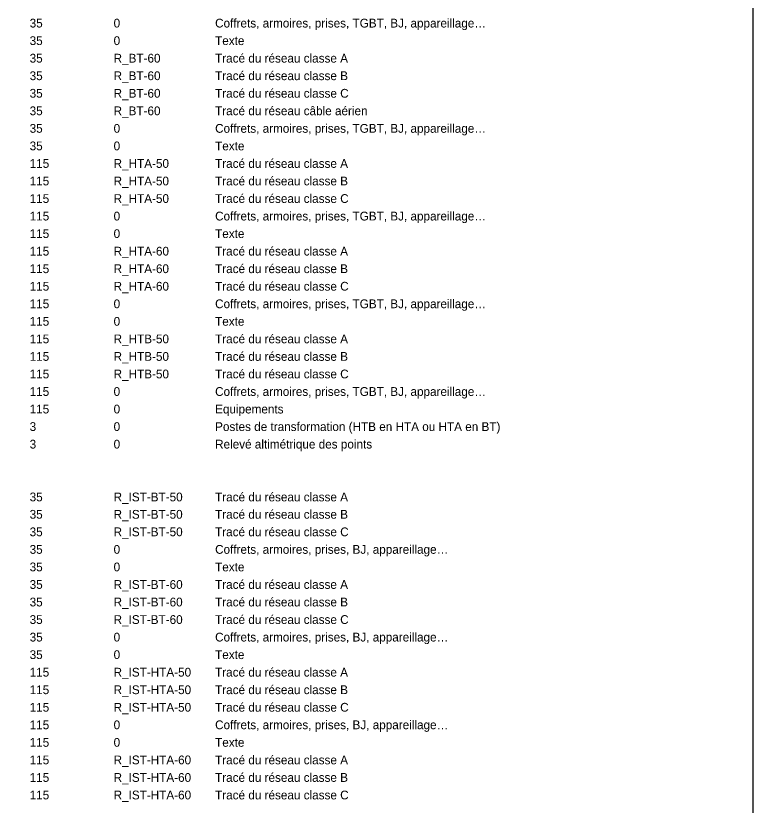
# Model space of a CAD drawing. Extents: x -60 to 214, y -380 to -21.
# Drawn here: x 72.77 to 114.84, y -110.94 to -65.94 of the extents above; entities that cross this region are included whole.
import ezdxf

# ---------------------------------------------------------------- set-up
doc = ezdxf.new("R2010")
doc.units = 0
for name, color, linetype in [('Default', 7, 'Continuous'), ('DH_TEXTE', 7, 'Continuous'), ('R_ELEC_ALT_POINT', 7, 'Continuous'), ('R_ELEC_BT_50HZ_EQUIP', 7, 'Continuous'), ('R_ELEC_BT_50HZ_TEXTE', 7, 'Continuous'), ('R_ELEC_BT_60HZ_EQUIP', 7, 'Continuous'), ('R_ELEC_BT_60HZ_LIAISON_CL_A', 7, 'Continuous'), ('R_ELEC_BT_60HZ_LIAISON_CL_B', 7, 'Continuous'), ('R_ELEC_BT_60HZ_LIAISON_CL_C', 7, 'Continuous'), ('R_ELEC_BT_60HZ_TEXTE', 7, 'Continuous'), ('R_ELEC_HTA_50HZ_EQUIP', 7, 'Continuous'), ('R_ELEC_HTA_50HZ_LIAISON_CL_A', 7, 'Continuous'), ('R_ELEC_HTA_50HZ_LIAISON_CL_B', 7, 'Continuous'), ('R_ELEC_HTA_50HZ_LIAISON_CL_C', 7, 'Continuous'), ('R_ELEC_HTA_50HZ_TEXTE', 7, 'Continuous'), ('R_ELEC_HTA_60HZ_EQUIP', 7, 'Continuous'), ('R_ELEC_HTA_60HZ_LIAISON_CL_A', 7, 'Continuous'), ('R_ELEC_HTA_60HZ_LIAISON_CL_B', 7, 'Continuous'), ('R_ELEC_HTA_60HZ_LIAISON_CL_C', 7, 'Continuous'), ('R_ELEC_HTA_60HZ_TEXTE', 7, 'Continuous'), ('R_ELEC_HTB_50HZ_EQUIP', 7, 'Continuous'), ('R_ELEC_HTB_50HZ_LIAISON_CL_A', 7, 'Continuous'), ('R_ELEC_HTB_50HZ_LIAISON_CL_B', 7, 'Continuous'), ('R_ELEC_HTB_50HZ_LIAISON_CL_C', 7, 'Continuous'), ('R_ELEC_HTB_50HZ_TEXTE', 7, 'Continuous'), ('R_ELEC_IST_BT_50HZ_EQUIP', 7, 'Continuous'), ('R_ELEC_IST_BT_50HZ_LIAISON_CL_A', 7, 'Continuous'), ('R_ELEC_IST_BT_50HZ_LIAISON_CL_B', 7, 'Continuous'), ('R_ELEC_IST_BT_50HZ_LIAISON_CL_C', 7, 'Continuous'), ('R_ELEC_IST_BT_50HZ_TEXTE', 7, 'Continuous'), ('R_ELEC_IST_BT_60HZ_EQUIP', 7, 'Continuous'), ('R_ELEC_IST_BT_60HZ_LIAISON_CL_A', 7, 'Continuous'), ('R_ELEC_IST_BT_60HZ_LIAISON_CL_B', 7, 'Continuous'), ('R_ELEC_IST_BT_60HZ_LIAISON_CL_C', 7, 'Continuous'), ('R_ELEC_IST_BT_60HZ_TEXTE', 7, 'Continuous'), ('R_ELEC_IST_HTA_50HZ_EQUIP', 7, 'Continuous'), ('R_ELEC_IST_HTA_50HZ_LIAISON_CL_A', 7, 'Continuous'), ('R_ELEC_IST_HTA_50HZ_LIAISON_CL_B', 7, 'Continuous'), ('R_ELEC_IST_HTA_50HZ_LIAISON_CL_C', 7, 'Continuous'), ('R_ELEC_IST_HTA_50HZ_TEXTE', 7, 'Continuous'), ('R_ELEC_IST_HTA_60HZ_LIAISON_CL_A', 7, 'Continuous'), ('R_ELEC_IST_HTA_60HZ_LIAISON_CL_B', 7, 'Continuous'), ('R_ELEC_IST_HTA_60HZ_LIAISON_CL_C', 7, 'Continuous'), ('R_ELEC_POSTE', 7, 'Continuous')]:
    doc.layers.add(name, color=color, linetype=linetype)

msp = doc.modelspace()

# ---------------------------------------------------------------- linework, layer by layer
at = {"layer": 'Default'}
msp.add_lwpolyline([(114.838, -25.727), (33.073, -25.727), (33.073, -380.216), (114.838, -380.216)], close=True, dxfattribs=at)

# ---------------------------------------------------------------- texts
at = {"layer": 'DH_TEXTE'}
for s, p in [('Tracé du réseau câble aérien ', (84.14, -71.61)), ('35 ', (73.561, -71.61)), ('R_BT-60 ', (78.351, -71.61))]:
    msp.add_text(s, height=0.5, dxfattribs=at).set_placement(p)
at = {"layer": 'R_ELEC_ALT_POINT'}
for s, p in [('3 ', (73.561, -90.61)), ('0 ', (78.351, -90.61)), ('Relevé altimétrique des points ', (84.14, -90.61))]:
    msp.add_text(s, height=0.5, dxfattribs=at).set_placement(p)
at = {"layer": 'R_ELEC_BT_50HZ_EQUIP'}
for s, p in [('35 ', (73.561, -66.61)), ('0 ', (78.351, -66.61)), ('Coffrets, armoires, prises, TGBT, BJ, appareillage…', (84.14, -66.61))]:
    msp.add_text(s, height=0.5, dxfattribs=at).set_placement(p)
at = {"layer": 'R_ELEC_BT_50HZ_TEXTE'}
for s, p in [('35 ', (73.561, -67.61)), ('0 ', (78.351, -67.61)), ('Texte ', (84.14, -67.61))]:
    msp.add_text(s, height=0.5, dxfattribs=at).set_placement(p)
at = {"layer": 'R_ELEC_BT_60HZ_EQUIP'}
for s, p in [('35 ', (73.561, -72.61)), ('0 ', (78.351, -72.61)), ('Coffrets, armoires, prises, TGBT, BJ, appareillage…', (84.14, -72.61))]:
    msp.add_text(s, height=0.5, dxfattribs=at).set_placement(p)
at = {"layer": 'R_ELEC_BT_60HZ_LIAISON_CL_A'}
for s, p in [('35 ', (73.561, -68.61)), ('R_BT-60 ', (78.351, -68.61)), ('Tracé du réseau classe A ', (84.14, -68.61))]:
    msp.add_text(s, height=0.5, dxfattribs=at).set_placement(p)
at = {"layer": 'R_ELEC_BT_60HZ_LIAISON_CL_B'}
for s, p in [('35 ', (73.561, -69.61)), ('R_BT-60 ', (78.351, -69.61)), ('Tracé du réseau classe B ', (84.14, -69.61))]:
    msp.add_text(s, height=0.5, dxfattribs=at).set_placement(p)
at = {"layer": 'R_ELEC_BT_60HZ_LIAISON_CL_C'}
for s, p in [('35 ', (73.561, -70.61)), ('R_BT-60 ', (78.351, -70.61)), ('Tracé du réseau classe C ', (84.14, -70.61))]:
    msp.add_text(s, height=0.5, dxfattribs=at).set_placement(p)
at = {"layer": 'R_ELEC_BT_60HZ_TEXTE'}
for s, p in [('35 ', (73.561, -73.61)), ('0 ', (78.351, -73.61)), ('Texte ', (84.14, -73.61))]:
    msp.add_text(s, height=0.5, dxfattribs=at).set_placement(p)
at = {"layer": 'R_ELEC_HTA_50HZ_EQUIP'}
for s, p in [('115 ', (73.561, -77.61)), ('0 ', (78.351, -77.61)), ('Coffrets, armoires, prises, TGBT, BJ, appareillage…', (84.14, -77.61))]:
    msp.add_text(s, height=0.5, dxfattribs=at).set_placement(p)
at = {"layer": 'R_ELEC_HTA_50HZ_LIAISON_CL_A'}
for s, p in [('115 ', (73.561, -74.61)), ('R_HTA-50 ', (78.351, -74.61)), ('Tracé du réseau classe A ', (84.14, -74.61))]:
    msp.add_text(s, height=0.5, dxfattribs=at).set_placement(p)
at = {"layer": 'R_ELEC_HTA_50HZ_LIAISON_CL_B'}
for s, p in [('115 ', (73.561, -75.61)), ('R_HTA-50 ', (78.351, -75.61)), ('Tracé du réseau classe B ', (84.14, -75.61))]:
    msp.add_text(s, height=0.5, dxfattribs=at).set_placement(p)
at = {"layer": 'R_ELEC_HTA_50HZ_LIAISON_CL_C'}
for s, p in [('115 ', (73.561, -76.61)), ('R_HTA-50 ', (78.351, -76.61)), ('Tracé du réseau classe C ', (84.14, -76.61))]:
    msp.add_text(s, height=0.5, dxfattribs=at).set_placement(p)
at = {"layer": 'R_ELEC_HTA_50HZ_TEXTE'}
for s, p in [('115 ', (73.561, -78.61)), ('0 ', (78.351, -78.61)), ('Texte ', (84.14, -78.61))]:
    msp.add_text(s, height=0.5, dxfattribs=at).set_placement(p)
at = {"layer": 'R_ELEC_HTA_60HZ_EQUIP'}
for s, p in [('115 ', (73.561, -82.61)), ('0 ', (78.351, -82.61)), ('Coffrets, armoires, prises, TGBT, BJ, appareillage…', (84.14, -82.61))]:
    msp.add_text(s, height=0.5, dxfattribs=at).set_placement(p)
at = {"layer": 'R_ELEC_HTA_60HZ_LIAISON_CL_A'}
for s, p in [('115 ', (73.561, -79.61)), ('R_HTA-60 ', (78.351, -79.61)), ('Tracé du réseau classe A ', (84.14, -79.61))]:
    msp.add_text(s, height=0.5, dxfattribs=at).set_placement(p)
at = {"layer": 'R_ELEC_HTA_60HZ_LIAISON_CL_B'}
for s, p in [('Tracé du réseau classe B ', (84.14, -80.61)), ('115 ', (73.561, -80.61)), ('R_HTA-60 ', (78.351, -80.61))]:
    msp.add_text(s, height=0.5, dxfattribs=at).set_placement(p)
at = {"layer": 'R_ELEC_HTA_60HZ_LIAISON_CL_C'}
for s, p in [('115 ', (73.561, -81.61)), ('R_HTA-60 ', (78.351, -81.61)), ('Tracé du réseau classe C ', (84.14, -81.61))]:
    msp.add_text(s, height=0.5, dxfattribs=at).set_placement(p)
at = {"layer": 'R_ELEC_HTA_60HZ_TEXTE'}
for s, p in [('115 ', (73.561, -83.61)), ('0 ', (78.351, -83.61)), ('Texte ', (84.14, -83.61))]:
    msp.add_text(s, height=0.5, dxfattribs=at).set_placement(p)
at = {"layer": 'R_ELEC_HTB_50HZ_EQUIP'}
for s, p in [('115 ', (73.561, -87.61)), ('0 ', (78.351, -87.61)), ('Coffrets, armoires, prises, TGBT, BJ, appareillage…', (84.14, -87.61))]:
    msp.add_text(s, height=0.5, dxfattribs=at).set_placement(p)
at = {"layer": 'R_ELEC_HTB_50HZ_LIAISON_CL_A'}
for s, p in [('115 ', (73.561, -84.61)), ('R_HTB-50 ', (78.351, -84.61)), ('Tracé du réseau classe A ', (84.14, -84.61))]:
    msp.add_text(s, height=0.5, dxfattribs=at).set_placement(p)
at = {"layer": 'R_ELEC_HTB_50HZ_LIAISON_CL_B'}
for s, p in [('115 ', (73.561, -85.61)), ('R_HTB-50 ', (78.351, -85.61)), ('Tracé du réseau classe B ', (84.14, -85.61))]:
    msp.add_text(s, height=0.5, dxfattribs=at).set_placement(p)
at = {"layer": 'R_ELEC_HTB_50HZ_LIAISON_CL_C'}
for s, p in [('115 ', (73.561, -86.61)), ('R_HTB-50 ', (78.351, -86.61)), ('Tracé du réseau classe C ', (84.14, -86.61))]:
    msp.add_text(s, height=0.5, dxfattribs=at).set_placement(p)
at = {"layer": 'R_ELEC_HTB_50HZ_TEXTE'}
for s, p in [('115 ', (73.561, -88.61)), ('0 ', (78.351, -88.61)), ('Equipements ', (84.14, -88.61))]:
    msp.add_text(s, height=0.5, dxfattribs=at).set_placement(p)
at = {"layer": 'R_ELEC_IST_BT_50HZ_EQUIP'}
for s, p in [('35 ', (73.561, -96.61)), ('0 ', (78.351, -96.61)), ('Coffrets, armoires, prises, BJ, appareillage…', (84.14, -96.61))]:
    msp.add_text(s, height=0.5, dxfattribs=at).set_placement(p)
at = {"layer": 'R_ELEC_IST_BT_50HZ_LIAISON_CL_A'}
for s, p in [('35 ', (73.561, -93.621)), ('R_IST-BT-50 ', (78.351, -93.621)), ('Tracé du réseau classe A', (84.14, -93.621))]:
    msp.add_text(s, height=0.5, dxfattribs=at).set_placement(p)
at = {"layer": 'R_ELEC_IST_BT_50HZ_LIAISON_CL_B'}
for s, p in [('35 ', (73.561, -94.61)), ('R_IST-BT-50 ', (78.351, -94.61)), ('Tracé du réseau classe B ', (84.14, -94.61))]:
    msp.add_text(s, height=0.5, dxfattribs=at).set_placement(p)
at = {"layer": 'R_ELEC_IST_BT_50HZ_LIAISON_CL_C'}
for s, p in [('35 ', (73.561, -95.61)), ('R_IST-BT-50 ', (78.351, -95.61)), ('Tracé du réseau classe C ', (84.14, -95.61))]:
    msp.add_text(s, height=0.5, dxfattribs=at).set_placement(p)
at = {"layer": 'R_ELEC_IST_BT_50HZ_TEXTE'}
for s, p in [('35 ', (73.561, -97.61)), ('0 ', (78.351, -97.61)), ('Texte ', (84.14, -97.61))]:
    msp.add_text(s, height=0.5, dxfattribs=at).set_placement(p)
at = {"layer": 'R_ELEC_IST_BT_60HZ_EQUIP'}
for s, p in [('35 ', (73.561, -101.61)), ('0 ', (78.351, -101.61)), ('Coffrets, armoires, prises, BJ, appareillage…', (84.14, -101.61))]:
    msp.add_text(s, height=0.5, dxfattribs=at).set_placement(p)
at = {"layer": 'R_ELEC_IST_BT_60HZ_LIAISON_CL_A'}
for s, p in [('Tracé du réseau classe A ', (84.14, -98.61)), ('35 ', (73.561, -98.61)), ('R_IST-BT-60 ', (78.351, -98.61))]:
    msp.add_text(s, height=0.5, dxfattribs=at).set_placement(p)
at = {"layer": 'R_ELEC_IST_BT_60HZ_LIAISON_CL_B'}
for s, p in [('35 ', (73.561, -99.61)), ('R_IST-BT-60 ', (78.351, -99.61)), ('Tracé du réseau classe B ', (84.14, -99.61))]:
    msp.add_text(s, height=0.5, dxfattribs=at).set_placement(p)
at = {"layer": 'R_ELEC_IST_BT_60HZ_LIAISON_CL_C'}
for s, p in [('35 ', (73.561, -100.61)), ('R_IST-BT-60 ', (78.351, -100.61)), ('Tracé du réseau classe C ', (84.14, -100.61))]:
    msp.add_text(s, height=0.5, dxfattribs=at).set_placement(p)
at = {"layer": 'R_ELEC_IST_BT_60HZ_TEXTE'}
for s, p in [('35 ', (73.561, -102.61)), ('0 ', (78.351, -102.61)), ('Texte ', (84.14, -102.61))]:
    msp.add_text(s, height=0.5, dxfattribs=at).set_placement(p)
at = {"layer": 'R_ELEC_IST_HTA_50HZ_EQUIP'}
for s, p in [('115 ', (73.561, -106.61)), ('0 ', (78.351, -106.61)), ('Coffrets, armoires, prises, BJ, appareillage…', (84.14, -106.61))]:
    msp.add_text(s, height=0.5, dxfattribs=at).set_placement(p)
at = {"layer": 'R_ELEC_IST_HTA_50HZ_LIAISON_CL_A'}
for s, p in [('115 ', (73.561, -103.61)), ('R_IST-HTA-50 ', (78.351, -103.61)), ('Tracé du réseau classe A ', (84.14, -103.61))]:
    msp.add_text(s, height=0.5, dxfattribs=at).set_placement(p)
at = {"layer": 'R_ELEC_IST_HTA_50HZ_LIAISON_CL_B'}
for s, p in [('115 ', (73.561, -104.61)), ('R_IST-HTA-50 ', (78.351, -104.61)), ('Tracé du réseau classe B ', (84.14, -104.61))]:
    msp.add_text(s, height=0.5, dxfattribs=at).set_placement(p)
at = {"layer": 'R_ELEC_IST_HTA_50HZ_LIAISON_CL_C'}
for s, p in [('115 ', (73.561, -105.61)), ('R_IST-HTA-50 ', (78.351, -105.61)), ('Tracé du réseau classe C ', (84.14, -105.61))]:
    msp.add_text(s, height=0.5, dxfattribs=at).set_placement(p)
at = {"layer": 'R_ELEC_IST_HTA_50HZ_TEXTE'}
for s, p in [('115 ', (73.561, -107.61)), ('0 ', (78.351, -107.61)), ('Texte ', (84.14, -107.61))]:
    msp.add_text(s, height=0.5, dxfattribs=at).set_placement(p)
at = {"layer": 'R_ELEC_IST_HTA_60HZ_LIAISON_CL_A'}
for s, p in [('115 ', (73.561, -108.61)), ('R_IST-HTA-60 ', (78.351, -108.61)), ('Tracé du réseau classe A ', (84.14, -108.61))]:
    msp.add_text(s, height=0.5, dxfattribs=at).set_placement(p)
at = {"layer": 'R_ELEC_IST_HTA_60HZ_LIAISON_CL_B'}
for s, p in [('115 ', (73.561, -109.61)), ('R_IST-HTA-60 ', (78.351, -109.61)), ('Tracé du réseau classe B ', (84.14, -109.61))]:
    msp.add_text(s, height=0.5, dxfattribs=at).set_placement(p)
at = {"layer": 'R_ELEC_IST_HTA_60HZ_LIAISON_CL_C'}
for s, p in [('115 ', (73.561, -110.61)), ('R_IST-HTA-60 ', (78.351, -110.61)), ('Tracé du réseau classe C ', (84.14, -110.61))]:
    msp.add_text(s, height=0.5, dxfattribs=at).set_placement(p)
at = {"layer": 'R_ELEC_POSTE'}
for s, p in [('Postes de transformation (HTB en HTA ou HTA en BT) ', (84.14, -89.61)), ('3 ', (73.561, -89.61)), ('0 ', (78.351, -89.61))]:
    msp.add_text(s, height=0.5, dxfattribs=at).set_placement(p)

doc.saveas('drawing.dxf')
